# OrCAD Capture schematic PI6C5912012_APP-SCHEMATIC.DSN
size B; title: PI6C5912012 Application Schematic; rev: 1.0; note: Diodes Inc. Clock IC Application Engineering
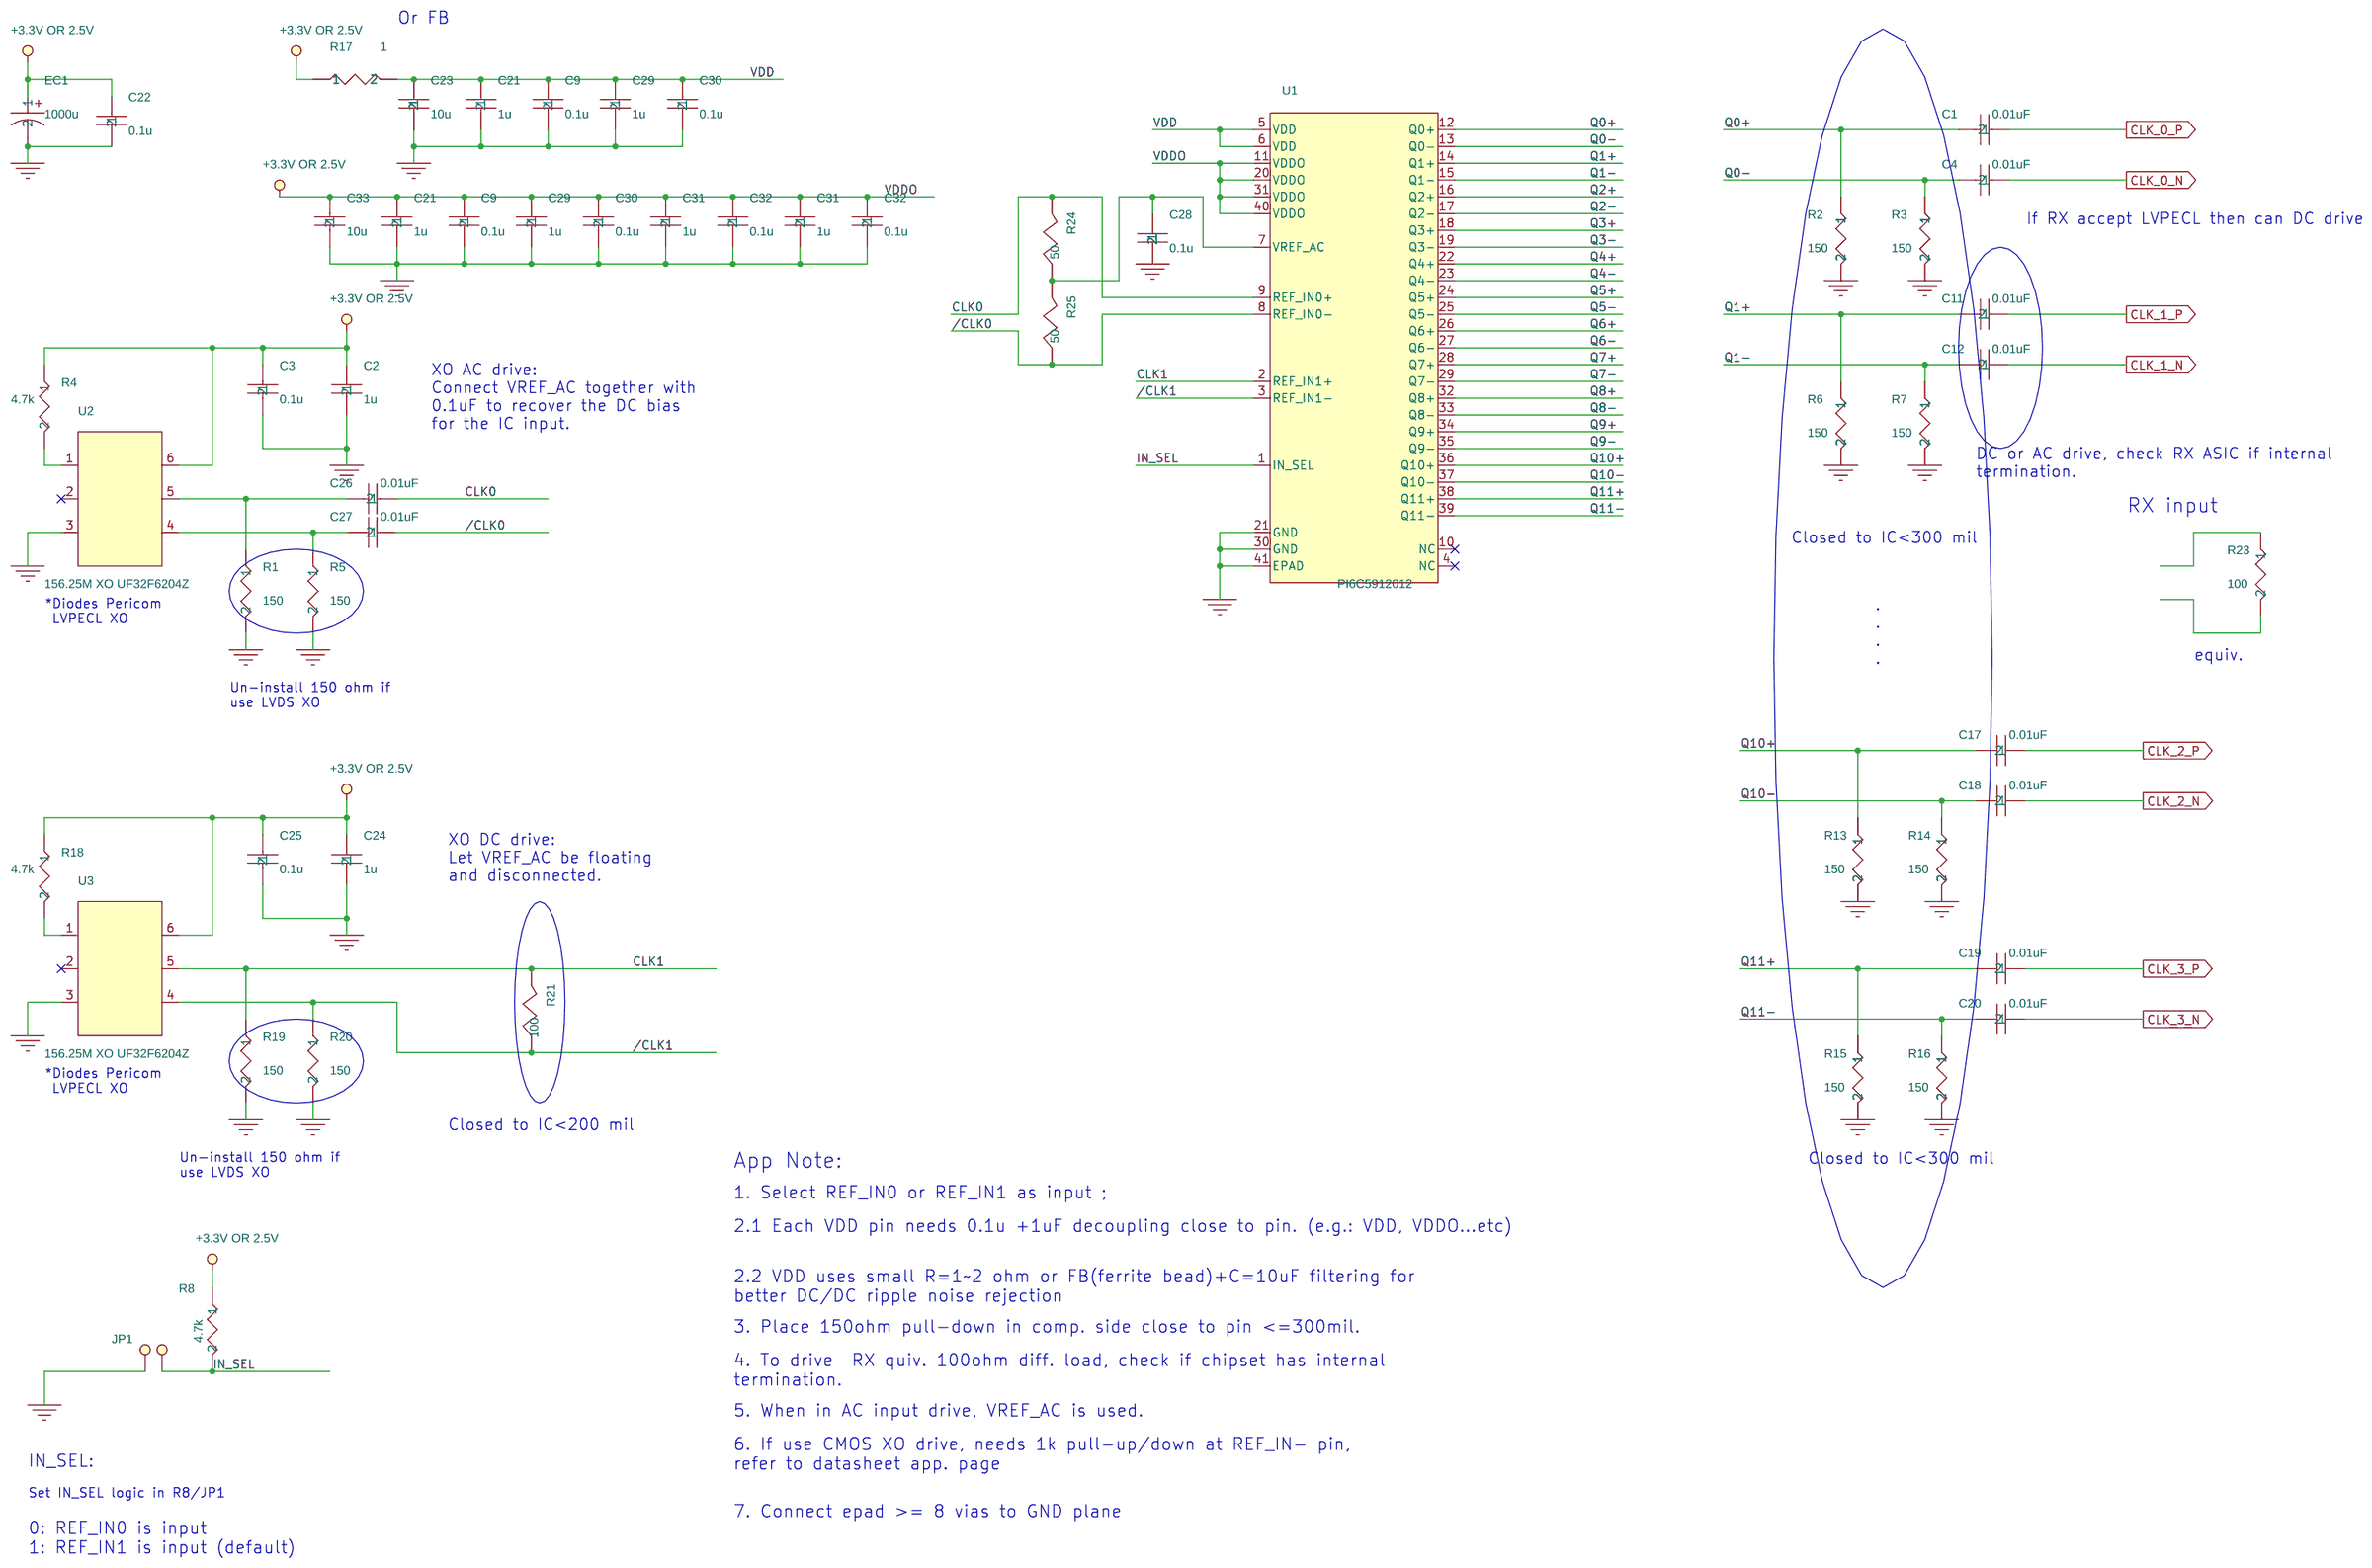
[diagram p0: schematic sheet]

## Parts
C1  0.01uF  [CC_0402]
C2  1u  [CC_0402]
C3  0.1u  [CC_0402]
C4  0.01uF  [CC_0402]
C9  0.1u  [CC_0402]
C9#2  0.1u  [CC_0402]
C11  0.01uF  [CC_0402]
C12  0.01uF  [CC_0402]
C17  0.01uF  [CC_0402]
C18  0.01uF  [CC_0402]
C19  0.01uF  [CC_0402]
C20  0.01uF  [CC_0402]
C21  1u  [CC_0805]
C21#2  1u  [CC_0805]
C22  0.1u  [CC_0402]
C23  10u  [CC_0805]
C24  1u  [CC_0402]
C25  0.1u  [CC_0402]
C26  0.01uF  [CC_0402]
C27  0.01uF  [CC_0402]
C28  0.1u  [CC_0402]
C29  1u  [CC_0805]
C29#2  1u  [CC_0805]
C30  0.1u  [CC_0402]
C30#2  0.1u  [CC_0402]
C31  1u  [CC_0805]
C31#2  1u  [CC_0805]
C32  0.1u  [CC_0402]
C32#2  0.1u  [CC_0402]
C33  10u  [CC_0805]
EC1  1000u  [CAP1000UF]
JP1  2x1 Pin Header  [2x1 Pin Header]
R1  150  [R_0402]
R2  150  [R_0402]
R3  150  [R_0402]
R4  4.7k  [R_0402]
R5  150  [R_0402]
R6  150  [R_0402]
R7  150  [R_0402]
R8  4.7k  [R_0402]
R13  150  [R_0402]
R14  150  [R_0402]
R15  150  [R_0402]
R16  150  [R_0402]
R17  1  [R_0402]
R18  4.7k  [R_0402]
R19  150  [R_0402]
R20  150  [R_0402]
R21  100
R23  100  [R_0402]
R24  50
R25  50
U1  PI6C5912012
U2  156.25M XO UF32F6204Z  [XO 5X7]
U3  156.25M XO UF32F6204Z  [XO 5X7]

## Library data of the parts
C1 = C_10n_0402
C2 C9#2 C30#2 C32#2 = C_0.1u_0402
C3 = C_0.1u_0402_11
C4 = C_10n_0402_3
C9 = C_0.1u_0402_7
C11 = C_10n_0402_4
C12 = C_10n_0402_2
C17 = C_10n_0402_8
C18 = C_10n_0402_7
C19 = C_10n_0402_9
C20 = C_10n_0402_1
C21 = C_1.0u_0805_6
C21#2 C23 C29#2 C31#2 = C_1.0u_0805
C22 = C_0.1u_0402_2
C24 = C_0.1u_0402_10
C25 = C_0.1u_0402_9
C26 = C_10n_0402_6
C27 = C_10n_0402_5
C28 = C_0.1u_0402_4
C29 = C_1.0u_0805_5
C30 = C_0.1u_0402_3
C31 = C_1.0u_0805_7
C32 = C_0.1u_0402_1
C33 = C_1.0u_0805_1
EC1 = C_alum_1000u
JP1 = 2x1_Pin_Header
R1 = R_0402
R2 = R_0_2
R3 = R_0_8
R4 = R_0402_2
R5 = R_0402_4
R6 = R_0_3
R7 = R_0_7
R8 = R_0402_7
R13 = R_0_6
R14 = R_0_4
R15 = R_0_5
R16 = R_0
R17 = R_0402_1
R18 = R_0402_6
R19 = R_0402_5
R20 = R_0402_3
R21 R24 R25 = res1
R23 = R_0_1
U1 = PI6C4911504-03_7
U2 U3 = XO_5X7

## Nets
+3.3V or 2.5V: C2.1 C3.1 C9.1 C21.1 C22.1 C24.1 C25.1 C29.1 C30.1 C31.1 C31#2.1 C32.1 C32#2.1 C33.1 EC1.1 R4.1 R8.1 R17.1 R18.1 U1.11(VDDO) U1.20(VDDO) U1.31(VDDO) U1.40(VDDO) U2.6 U3.6
GND: C2.2 C3.2 C9.2 C9#2.2 C21.2 C21#2.2 C22.2 C23.2 C24.2 C25.2 C28.2 C29.2 C29#2.2 C30.2 C30#2.2 C31.2 C31#2.2 C32.2 C32#2.2 C33.2 EC1.2 JP1.1 R1.2 R2.2 R3.2 R5.2 R6.2 R7.2 R13.2 R14.2 R15.2 R16.2 R19.2 R20.2 U1.21(GND) U1.30(GND) U1.41(EPAD) U2.3 U3.3
VDD: C9#2.1 C21#2.1 C23.1 C29#2.1 C30#2.1 R17.2 U1.5(VDD) U1.6(VDD)
/CLK0: C27.1 R25.1 U1.8(REF_IN0-)
/CLK1: R20.1 R21.1 U1.3(REF_IN1-) U3.4
CLK0: C26.1 R24.2 U1.9(REF_IN0+)
CLK1: R19.1 R21.2 U1.2(REF_IN1+) U3.5
CLK_0_N: C4.1
CLK_0_P: C1.1
CLK_1_N: C12.1
CLK_1_P: C11.1
CLK_2_N: C18.1
CLK_2_P: C17.1
CLK_3_N: C20.1
CLK_3_P: C19.1
IN_SEL: JP1.2 R8.2 U1.1(IN_SEL)
Q0+: C1.2 R2.1 U1.12(Q0+)
Q0-: C4.2 R3.1 U1.13(Q0-)
Q1+: C11.2 R6.1 U1.14(Q1+)
Q1-: C12.2 R7.1 U1.15(Q1-)
Q2+: U1.16(Q2+)
Q2-: U1.17(Q2-)
Q3+: U1.18(Q3+)
Q3-: U1.19(Q3-)
Q4+: U1.22(Q4+)
Q4-: U1.23(Q4-)
Q5+: U1.24(Q5+)
Q5-: U1.25(Q5-)
Q6+: U1.26(Q6+)
Q6-: U1.27(Q6-)
Q7+: U1.28(Q7+)
Q7-: U1.29(Q7-)
Q8+: U1.32(Q8+)
Q8-: U1.33(Q8-)
Q9+: U1.34(Q9+)
Q9-: U1.35(Q9-)
Q10+: C17.2 R13.1 U1.36(Q10+)
Q10-: C18.2 R14.1 U1.37(Q10-)
Q11+: C19.2 R15.1 U1.38(Q11+)
Q11-: C20.2 R16.1 U1.39(Q11-)
N4609914: R18.2 U3.1
N4633501: C27.2 R5.1 U2.4
N4633505: C26.2 R1.1 U2.5
N4633537: R4.2 U2.1
N4657915: C28.1 R24.1 R25.2 U1.7(VREF_AC)

Not connected (* = marked no-connect by the designer): R23 1 2; U1 4(NC)* 10(NC)*; U2 2*; U3 2*

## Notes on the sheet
- Or FB
- If RX accept LVPECL then can DC drive
- XO AC drive:
  Connect VREF_AC together with
  0.1uF to recover the DC bias
  for the IC input.
- DC or AC drive, check RX ASIC if internal
  termination.
- RX input
- Closed to IC<300 mil
- *Diodes Pericom
   LVPECL XO
- .
  .
  .
  .
- equiv.
- Un-install 150 ohm if
  use LVDS XO
- XO DC drive:
  Let VREF_AC be floating
  and disconnected.
- *Diodes Pericom
   LVPECL XO
- Closed to IC<200 mil
- Un-install 150 ohm if
  use LVDS XO
- App Note:
- Closed to IC<300 mil
- 1. Select REF_IN0 or REF_IN1 as input ;
- 2.1 Each VDD pin needs 0.1u +1uF decoupling close to pin. (e.g.: VDD, VDDO...etc)
- 2.2 VDD uses small R=1~2 ohm or FB(ferrite bead)+C=10uF filtering for
  better DC/DC ripple noise rejection
- 3. Place 150ohm pull-down in comp. side close to pin <=300mil.
- 4. To drive  RX quiv. 100ohm diff. load, check if chipset has internal
  termination.
- 5. When in AC input drive, VREF_AC is used.
- 6. If use CMOS XO drive, needs 1k pull-up/down at REF_IN- pin,
  refer to datasheet app. page
- IN_SEL:
- Set IN_SEL logic in R8/JP1
- 7. Connect epad >= 8 vias to GND plane
- 0: REF_IN0 is input
  1: REF_IN1 is input (default)
